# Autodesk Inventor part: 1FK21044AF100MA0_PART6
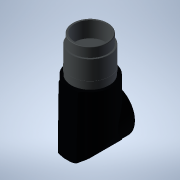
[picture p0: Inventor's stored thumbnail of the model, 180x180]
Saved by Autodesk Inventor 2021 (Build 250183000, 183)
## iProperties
Created: 2025-04
Part Number: 1FK21044AF100MA0_PART6
Material: Generic
Catalog Web Link: www.3dfindit.com
Description: -Servo synchronous motor
Document SubType Name: Modeling
Designer: psAdmin
Mass: 11.0817 g
Surface Area: 35.706 cm^2
Volume: 11.0817 cm^3
Density: 1 g/cm^3
Appearance: PSOLRGB-176-176-176
Category: PARTsolutions
Title: 1FK21044AF100MA0_PART6
Author: Cadenas PARTsolutions
Comments: Servo synchronous motor
Sending System: PARTsolutions
Preprocessor: ST-DEVELOPER v19.3
PSOL_IDENT_0: {$CADENAS_DATA/23d-libs/siemens_ag/_cat_/ec/e4/1fk21044af100ma0.prj},213 {VTYP=3D},{NB=1FK21044AF100
PSOL_IDENT_1: MA0_PART6},{LINA=1FK21044AF100MA0_PART6},{NN=1FK21044AF100MA0_PART6},{NOPRJ=TRUE},{DATE=19.08.2025 1
PSOL_IDENT_2: 4:01:05},{GEOMDATE=30.07.2025 02:01:01},{VERSION=},{LINEID=10},{WBVAR=},{WBNUMERIC=}  {NB=1FK21044AF
PSOL_IDENT_3: 100MA0_PART6},{LINA=1FK21044AF100MA0_PART6},{KT=DUMMY},{PREVIEW=../../../_pool_/cb/72/p_d211_xx_0043
PSOL_IDENT_4: 4j.png},{DESCSHORT=SIMOTICS S-1FK2 HD, SINAMICS S210 3AC 400V-480V, 1.27 Nm, 3000 rpm},{DESCLONG=SIM
PSOL_IDENT_5: OTICS S-1FK2 HD servo motor M0=1.27 Nm; PN = 0.4 kW at nN=3000 rpm (380-480 V); PN = 0.2 kW at nN=15
PSOL_IDENT_6: 00 rpm (200-240 V); with holding brake; degree of protection IP64; cylindrical shaft D19x40mm; absol
PSOL_IDENT_7: ute encoder 22-bit + 12-bit multiturn (encoder AM22DQC); with OCC interface; plug size M17, rotatabl
PSOL_IDENT_8: e; SIMOTICS S-1FK2 servomotorfor a wide range of uses in industrial environments. SIMOTICS S‑1FK2 se
PSOL_IDENT_9: rvomotors are compact synchronous motors with a high dynamic performance that set themselves apart a
PSOL_IDENT_10: s a result of their high power density, degree of protection and overload capability. The motors are
PSOL_IDENT_11: available in two variants: as High Dynamic variant (highest dynamic performance as a result of the
PSOL_IDENT_12: low intrinsic moment of inertia for applications demanding a high dynamic performance with low moved
PSOL_IDENT_13: masses) - and as Compact variant (precise and stable closed-loop control for medium up to large mov
PSOL_IDENT_14: ed masses as a result of a medium intrinsic moment of inertia). SIMOTICSS‑1FK2 servomotors fully exp
PSOL_IDENT_15: loit their strengths in a system with the SINAMICSS210 frequency converter and simple connection usi
PSOL_IDENT_16: ng the one cable connection (OCC). Advantages include the short control and positioning times, fast
PSOL_IDENT_17: and precise correction of disturbing quantities as well as stable control with a high dynamic perfor
PSOL_IDENT_18: mance. The servo motors can be configured to address a wide range of requirements. For example with
PSOL_IDENT_19: and without holding brake, IP64 or IP65 degree of protection, singleturn or multiturn absolute encod
PSOL_IDENT_20: ers - to name just a few. Further, the servomotors are available in different shaft heights extendin
PSOL_IDENT_21: g from 20 to 100. A shaft sealing ring is available to achieve an IP65 degree of protection and for
PSOL_IDENT_22: subsequent mounting at the motor or as spare part. SIMOTICS - the optimum motor for each and every m
PSOL_IDENT_23: otion control application.},{INTNO=195125043275},{SUPPLIERALTNO=1FK2104-4AF10-0MA0},{MANUID=1FK21044
PSOL_IDENT_24: AF100MA0},{MANUNAME=Siemens},{MANUTYPEDESC=Synchronous motor 1FK2-HD 1.27 NM},{AAU732=SIMOTICS},{AAO
PSOL_IDENT_25: 057=S-1FK2},{AAU734=SIMOTICS S-1FK2 HD servo motor M0=1.27 Nm; PN = 0.4 kW at nN=3000 rpm (380-480 V
PSOL_IDENT_26: ); PN = 0.2 kW at nN=1500 rpm (200-240 V); with holding brake; degree of protection IP64; cylindrica
PSOL_IDENT_27: l shaft D19x40mm; absolute encoder 22-bit + 12-bit multiturn (encoder AM22DQC); with OCC interface;
PSOL_IDENT_28: plug size M17, rotatable;},{AAW338=Synchronous motor 1FK2-HD 1.27 NM},{AAO742=SIMOTICS},{AAO663=4042
PSOL_IDENT_29: 948694015},{NOCUPEROU=1},{PRICEQUANTITY=1},{QUANTITYMIN=1},{QUANTITYINT=1},{CTN=85015100},{COO=DE},{
PSOL_IDENT_30: AAO676=1FK2104-4AF10-0MA0},{AAO677=Siemens AG},{ORDERUNIT=C62},{CONTENTUNIT=C62}
NB: 1FK21044AF100MA0_PART6
NT: Servo synchronous motor
NBSYN: $MANUID._PART6
LINA: 1FK21044AF100MA0_PART6
CATALOG: SIEMENS
PREVIEW: ../../../_pool_/cb/72/p_d211_xx_00434j.png
DESCSHORT: SIMOTICS S-1FK2 HD, SINAMICS S210 3AC 400V-480V, 1.27 Nm, 3000 rpm
DESCLONG: SIMOTICS S-1FK2 HD servo motor M0=1.27 Nm; PN = 0.4 kW at nN=3000 rpm (380-480 V); PN = 0.2 kW at nN=1500 rpm (200-240 V); with holding brake; degree of protect
INTNO: 195125043275
SUPPLIERALTNO: 1FK2104-4AF10-0MA0
MANUID: 1FK21044AF100MA0
MANUNAME: Siemens
MANUTYPEDESC: Synchronous motor 1FK2-HD 1.27 NM
AAU732: SIMOTICS
AAO057: S-1FK2
AAU734: SIMOTICS S-1FK2 HD servo motor M0=1.27 Nm; PN = 0.4 kW at nN=3000 rpm (380-480 V); PN = 0.2 kW at nN=1500 rpm (200-240 V); with holding brake; degree of protect
AAW338: Synchronous motor 1FK2-HD 1.27 NM
AAO742: SIMOTICS
AAO663: 4042948694015.0
NOCUPEROU: 1
PRICEQUANTITY: 1
QUANTITYMIN: 1
QUANTITYINT: 1
CTN: 85015100
COO: DE
ARTICLENO: 1FK21044AF100MA0_PART6
BOMINFO: 1FK21044AF100MA0_PART6
CREATOR: CADENAS GmbH
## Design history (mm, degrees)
feature "2025_04_17_15_33_01_0642"
body "Solid1"
